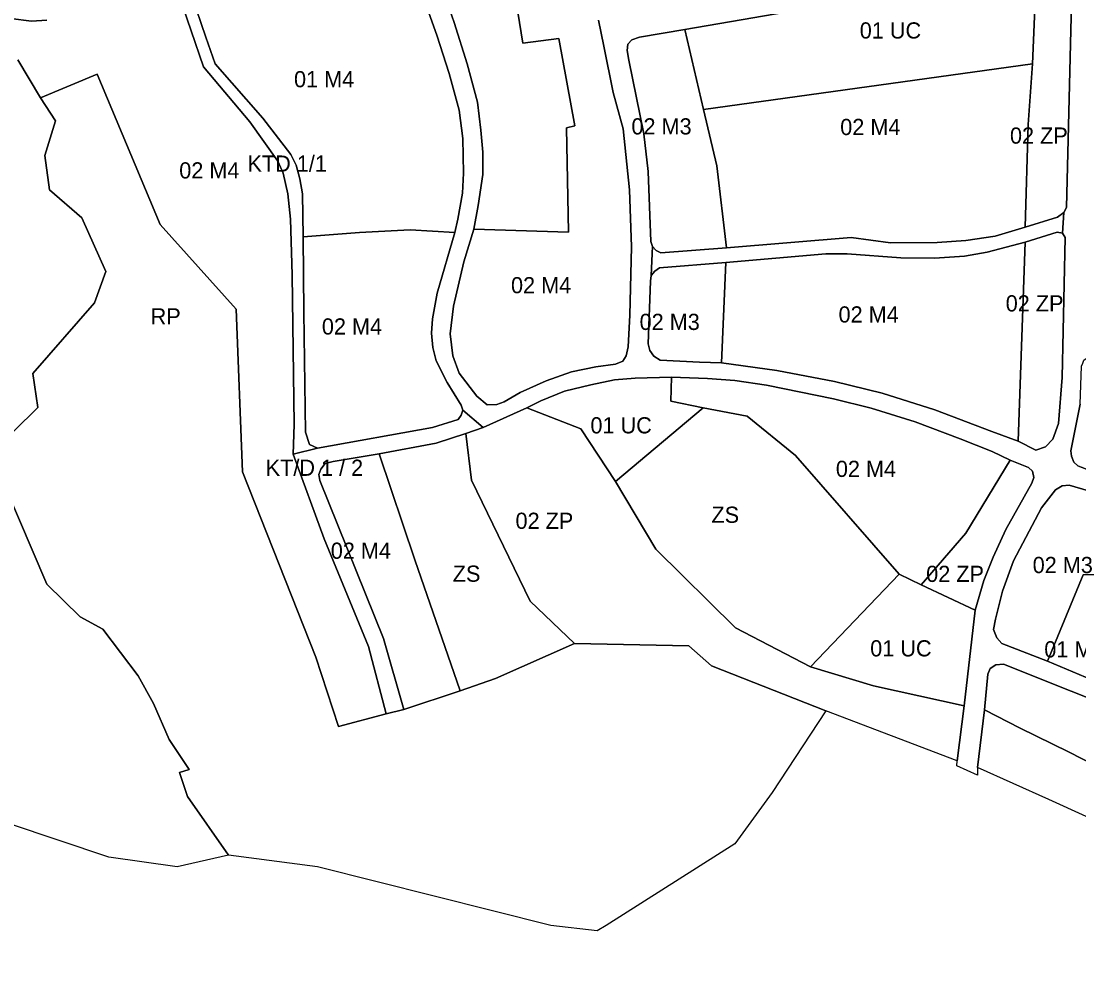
# Model space of a CAD drawing. Extents: x 7419295 to 7421535, y 5544294 to 5545394.
# Drawn here: x 7420075 to 7420728, y 5544294 to 5544875 of the extents above; entities that cross this region are included whole.
import ezdxf

# ---------------------------------------------------------------- set-up
doc = ezdxf.new("R2010")
doc.units = 0
doc.layers.add('linie_rozgraniczajace', color=7, linetype='Continuous')
doc.layers.add('oznaczenia_przeznaczen', color=7, linetype='Continuous')

msp = doc.modelspace()

# ---------------------------------------------------------------- linework, layer by layer
at = {"layer": 'linie_rozgraniczajace'}
for points in [[(7420374.46, 5544927.64), (7420385.1, 5544861.32), (7420407.25, 5544864.01), (7420417.22, 5544810.2), (7420412.02, 5544808.94), (7420413.37, 5544744.51), (7420354.78, 5544746.31), (7420357.53, 5544760.98), (7420360.41, 5544780.03), (7420360.33, 5544793.87), (7420359.14, 5544807.54), (7420357.01, 5544824.75), (7420350.66, 5544848.44), (7420342.78, 5544874.06), (7420338.31, 5544886.26)], [(7420431.9, 5544875.41), (7420435.21, 5544859.45), (7420440.83, 5544830.75), (7420446.99, 5544808.25), (7420450.9, 5544770.69), (7420452.17, 5544735.47), (7420451.18, 5544693.29), (7420450.07, 5544673.71), (7420448.87, 5544668), (7420446.77, 5544664.78), (7420442.4, 5544662.96), (7420430.22, 5544661.27), (7420415.08, 5544658.12), (7420399.56, 5544652.72), (7420383.48, 5544645.51), (7420373.54, 5544639.59), (7420369.03, 5544637.93), (7420363.15, 5544637.84), (7420356.74, 5544643.09), (7420345.82, 5544657.41), (7420341.89, 5544668.14), (7420340.22, 5544681.64), (7420342.23, 5544698.72), (7420348.6, 5544726.22), (7420354.78, 5544746.31), (7420413.37, 5544744.51), (7420412.02, 5544808.94), (7420417.22, 5544810.2), (7420407.25, 5544864.01), (7420385.1, 5544861.32), (7420374.46, 5544927.64)], [(7420165.01, 5544913.57), (7420187.81, 5544846.67), (7420216.52, 5544812.6), (7420233.88, 5544788.26), (7420237.03, 5544780.84), (7420240.08, 5544768.14), (7420241.67, 5544752.56), (7420242.75, 5544718.16), (7420243.81, 5544625.59), (7420243.27, 5544607.43), (7420262.51, 5544555.08), (7420289.85, 5544488.58), (7420300.75, 5544446.91), (7420271.19, 5544439.15), (7420257.37, 5544481.96), (7420211.94, 5544596.44), (7420208.05, 5544696.89), (7420161.14, 5544749.31), (7420122.29, 5544841.99), (7420087.27, 5544827.45), (7420073.18, 5544850.83)], [(7420327.05, 5544879.92), (7420332.06, 5544866.11), (7420339.7, 5544842.42), (7420345.83, 5544819.78), (7420348.12, 5544802.43), (7420348.52, 5544780.83), (7420347.91, 5544768.5), (7420344.9, 5544752.58), (7420343.05, 5544744.3), (7420315.48, 5544746.02), (7420284.29, 5544744.29), (7420249.53, 5544741.55), (7420249.09, 5544768.07), (7420247.44, 5544777.4), (7420245.19, 5544785.8), (7420241.9, 5544792.53), (7420224.45, 5544814.92), (7420195.18, 5544848.39), (7420189.26, 5544864.99), (7420171.71, 5544917.12)], [(7420702.29, 5544907.09), (7420485.05, 5544869.73), (7420457.22, 5544865), (7420452.36, 5544863.31), (7420449.93, 5544860.53), (7420449.61, 5544856.64), (7420450.64, 5544850.72), (7420459.8, 5544805.21), (7420462.48, 5544782.05), (7420464.24, 5544738.77), (7420465.17, 5544735.53), (7420464.43, 5544717.7), (7420463.93, 5544714.25), (7420462.48, 5544675.57), (7420463.44, 5544671.44), (7420465.97, 5544667.81), (7420469.89, 5544665.43), (7420494.27, 5544664.19), (7420507.8, 5544663.69), (7420542.02, 5544659.12), (7420577.6, 5544652.21), (7420607.03, 5544645.1), (7420639.57, 5544634.79), (7420674.62, 5544621.3), (7420690.93, 5544615.3), (7420701.8, 5544609.92), (7420707.76, 5544611.96), (7420712.34, 5544616.62), (7420715.92, 5544626.3), (7420718.1, 5544654.8), (7420719.99, 5544741.28), (7420718.29, 5544743.9), (7420719.21, 5544756.58), (7420720.83, 5544759.77), (7420724.4, 5544903.07)], [(7420338.31, 5544886.26), (7420342.78, 5544874.06), (7420350.66, 5544848.44), (7420357.01, 5544824.75), (7420359.14, 5544807.54), (7420360.33, 5544793.87), (7420360.41, 5544780.03), (7420357.53, 5544760.98), (7420354.78, 5544746.31), (7420348.6, 5544726.22), (7420342.23, 5544698.72), (7420340.22, 5544681.64), (7420341.89, 5544668.14), (7420345.82, 5544657.41), (7420356.74, 5544643.09), (7420363.15, 5544637.84), (7420369.03, 5544637.93), (7420373.54, 5544639.59), (7420383.48, 5544645.51), (7420399.56, 5544652.72), (7420415.08, 5544658.12), (7420430.22, 5544661.27), (7420442.4, 5544662.96), (7420446.77, 5544664.78), (7420448.87, 5544668), (7420450.07, 5544673.71), (7420451.18, 5544693.29), (7420452.17, 5544735.47), (7420450.9, 5544770.69), (7420446.99, 5544808.25), (7420440.83, 5544830.75), (7420435.21, 5544859.45), (7420431.9, 5544875.41)], [(7420765.57, 5544444.2), (7420681.96, 5544477.58), (7420677.2, 5544477.24), (7420673.64, 5544475.01), (7420672.35, 5544471.53), (7420670.12, 5544449.36), (7420665.8, 5544413.78), (7420665.83, 5544409.16), (7420653.2, 5544414.91), (7420653.23, 5544417.89), (7420657.65, 5544451.83), (7420664.46, 5544510.93), (7420669.76, 5544529.29), (7420675.54, 5544543.69), (7420683.27, 5544560.85), (7420699.43, 5544589.53), (7420700.72, 5544593.01), (7420699.93, 5544596.85), (7420697.45, 5544599.14), (7420686.14, 5544603.55), (7420674.96, 5544608.91), (7420655.08, 5544616.9), (7420627.32, 5544627.25), (7420600.18, 5544635.81), (7420576.9, 5544641.58), (7420535.55, 5544649.89), (7420516.03, 5544652.82), (7420499.19, 5544654.08), (7420476.85, 5544654.96), (7420454.46, 5544654.34), (7420441.63, 5544653.23), (7420427.13, 5544650.25), (7420410.81, 5544646.17), (7420396.27, 5544640.21), (7420387.62, 5544636.01), (7420360.62, 5544623.73), (7420348.1, 5544634.49), (7420347.02, 5544637.58), (7420338.34, 5544651.69), (7420331.61, 5544664.91), (7420329.53, 5544673.17), (7420328.69, 5544682.08), (7420329.28, 5544690.9), (7420332.14, 5544706.82), (7420343.05, 5544744.3), (7420344.9, 5544752.58), (7420347.91, 5544768.5), (7420348.52, 5544780.83), (7420348.12, 5544802.43), (7420345.83, 5544819.78), (7420339.7, 5544842.42), (7420332.06, 5544866.11), (7420327.05, 5544879.92)], [(7420091.1, 5544875.41), (7420081.59, 5544874.72), (7420068.64, 5544876.43)], [(7420068.64, 5544876.43), (7420081.59, 5544874.72), (7420091.1, 5544875.41)], [(7420073.18, 5544850.83), (7420087.27, 5544827.45), (7420096.43, 5544813.21), (7420089.83, 5544791.78), (7420092.76, 5544770.63), (7420112.86, 5544753.26), (7420127.55, 5544720.18), (7420120.54, 5544700.9), (7420082.58, 5544657.18), (7420085.66, 5544636.14), (7420070.72, 5544621.63)], [(7420070.72, 5544621.63), (7420085.66, 5544636.14), (7420082.58, 5544657.18), (7420120.54, 5544700.9), (7420127.55, 5544720.18), (7420112.86, 5544753.26), (7420092.76, 5544770.63), (7420089.83, 5544791.78), (7420096.43, 5544813.21), (7420087.27, 5544827.45), (7420122.29, 5544841.99), (7420161.14, 5544749.31), (7420208.05, 5544696.89), (7420211.94, 5544596.44), (7420257.37, 5544481.96), (7420271.19, 5544439.15), (7420300.75, 5544446.91), (7420311.61, 5544449.59), (7420346.34, 5544461.24), (7420368.29, 5544468.84), (7420417.09, 5544490.35), (7420487.55, 5544489.03), (7420501.68, 5544476.53), (7420572.17, 5544448.84), (7420539.01, 5544398.27), (7420516.02, 5544366.62), (7420436.53, 5544316.31), (7420430.9, 5544312.97), (7420402.38, 5544316.13), (7420258.34, 5544352.37), (7420203.36, 5544359.58), (7420178.05, 5544395.97), (7420172.99, 5544410.81), (7420179.12, 5544412.6), (7420166.61, 5544431.02), (7420157.12, 5544453.29), (7420147.52, 5544470.49), (7420125.74, 5544499.19), (7420111.76, 5544506.96), (7420091.08, 5544526.99), (7420065.25, 5544587.88)], [(7420729.31, 5544638.3), (7420723.57, 5544609.33), (7420723.82, 5544606.16), (7420725.42, 5544602.47), (7420727.82, 5544600.06), (7420742.24, 5544594.51)], [(7420065.25, 5544587.88), (7420091.08, 5544526.99), (7420111.76, 5544506.96), (7420125.74, 5544499.19), (7420147.52, 5544470.49), (7420157.12, 5544453.29), (7420166.61, 5544431.02), (7420179.12, 5544412.6), (7420172.99, 5544410.81), (7420178.05, 5544395.97), (7420203.36, 5544359.58), (7420171.7, 5544352.49), (7420129.5, 5544358.52), (7420067.4, 5544379.25)], [(7420734.48, 5544584.68), (7420722.45, 5544588.18), (7420718.1, 5544587.89), (7420713.96, 5544585.33), (7420705.31, 5544574.17), (7420688.09, 5544541.39), (7420681.32, 5544522.77), (7420676.93, 5544505.53), (7420675.74, 5544499), (7420677.76, 5544493.96), (7420680.94, 5544490.34), (7420709.11, 5544479.54), (7420748.11, 5544463.04)], [(7420747.77, 5544410.39), (7420722.04, 5544423.59), (7420692.2, 5544438.03), (7420670.12, 5544449.36), (7420672.35, 5544471.53), (7420673.64, 5544475.01), (7420677.2, 5544477.24), (7420681.96, 5544477.58), (7420765.57, 5544444.2)]]:
    msp.add_lwpolyline(points, dxfattribs=at)
for points in [[(7420171.71, 5544917.12), (7420189.26, 5544864.99), (7420195.18, 5544848.39), (7420224.45, 5544814.92), (7420241.9, 5544792.53), (7420245.19, 5544785.8), (7420247.44, 5544777.4), (7420249.09, 5544768.07), (7420249.53, 5544741.55), (7420249.89, 5544695.06), (7420250.83, 5544620.86), (7420253.36, 5544613.36), (7420258.39, 5544611.02), (7420243.27, 5544607.43), (7420243.81, 5544625.59), (7420242.75, 5544718.16), (7420241.67, 5544752.56), (7420240.08, 5544768.14), (7420237.03, 5544780.84), (7420233.88, 5544788.26), (7420216.52, 5544812.6), (7420187.81, 5544846.67), (7420165.01, 5544913.57)], [(7420702.29, 5544907.09), (7420699.74, 5544848.48), (7420496.72, 5544820.31), (7420485.05, 5544869.73)], [(7420702.29, 5544907.09), (7420715.71, 5544909.42), (7420719.53, 5544909.43), (7420722.29, 5544907.9), (7420724.4, 5544903.07), (7420720.83, 5544759.77), (7420719.21, 5544756.58), (7420715.35, 5544753.73), (7420695.25, 5544747.55), (7420697.13, 5544811), (7420699.74, 5544848.48)], [(7420485.05, 5544869.73), (7420496.72, 5544820.31), (7420504.95, 5544785.44), (7420510.96, 5544734.83), (7420470.25, 5544731.71), (7420467.34, 5544733.08), (7420465.17, 5544735.53), (7420464.24, 5544738.77), (7420462.48, 5544782.05), (7420459.8, 5544805.21), (7420450.64, 5544850.72), (7420449.61, 5544856.64), (7420449.93, 5544860.53), (7420452.36, 5544863.31), (7420457.22, 5544865)], [(7420699.74, 5544848.48), (7420697.13, 5544811), (7420695.25, 5544747.55), (7420676.71, 5544742.06), (7420658.7, 5544739.24), (7420641.01, 5544738.07), (7420612.09, 5544737.79), (7420587.78, 5544741.13), (7420510.96, 5544734.83), (7420504.95, 5544785.44), (7420496.72, 5544820.31)], [(7420719.21, 5544756.58), (7420718.29, 5544743.9), (7420715.09, 5544744.51), (7420695.3, 5544738.34), (7420671.89, 5544732.1), (7420657.84, 5544729.59), (7420639.28, 5544728.39), (7420618.6, 5544728.6), (7420585.42, 5544731.13), (7420572.17, 5544731.02), (7420510.37, 5544725.82), (7420469.48, 5544722.38), (7420466.54, 5544720.47), (7420464.43, 5544717.7), (7420465.17, 5544735.53), (7420467.34, 5544733.08), (7420470.25, 5544731.71), (7420510.96, 5544734.83), (7420587.78, 5544741.13), (7420612.09, 5544737.79), (7420641.01, 5544738.07), (7420658.7, 5544739.24), (7420676.71, 5544742.06), (7420695.25, 5544747.55), (7420715.35, 5544753.73)], [(7420249.53, 5544741.55), (7420284.29, 5544744.29), (7420315.48, 5544746.02), (7420343.05, 5544744.3), (7420332.14, 5544706.82), (7420329.28, 5544690.9), (7420328.69, 5544682.08), (7420329.53, 5544673.17), (7420331.61, 5544664.91), (7420338.34, 5544651.69), (7420347.02, 5544637.58), (7420348.1, 5544634.49), (7420347.11, 5544631.47), (7420345.16, 5544628.71), (7420329.3, 5544623.74), (7420258.39, 5544611.02), (7420253.36, 5544613.36), (7420250.83, 5544620.86), (7420249.89, 5544695.06)], [(7420695.3, 5544738.34), (7420715.09, 5544744.51), (7420718.29, 5544743.9), (7420719.99, 5544741.28), (7420718.1, 5544654.8), (7420715.92, 5544626.3), (7420712.34, 5544616.62), (7420707.76, 5544611.96), (7420701.8, 5544609.92), (7420690.93, 5544615.3)], [(7420695.3, 5544738.34), (7420690.93, 5544615.3), (7420674.62, 5544621.3), (7420639.57, 5544634.79), (7420607.03, 5544645.1), (7420577.6, 5544652.21), (7420542.02, 5544659.12), (7420507.8, 5544663.69), (7420510.37, 5544725.82), (7420572.17, 5544731.02), (7420585.42, 5544731.13), (7420618.6, 5544728.6), (7420639.28, 5544728.39), (7420657.84, 5544729.59), (7420671.89, 5544732.1)], [(7420510.37, 5544725.82), (7420507.8, 5544663.69), (7420494.27, 5544664.19), (7420469.89, 5544665.43), (7420465.97, 5544667.81), (7420463.44, 5544671.44), (7420462.48, 5544675.57), (7420463.93, 5544714.25), (7420464.43, 5544717.7), (7420466.54, 5544720.47), (7420469.48, 5544722.38)], [(7420729.8, 5544599.3), (7420727.82, 5544600.06), (7420725.42, 5544602.47), (7420723.82, 5544606.16), (7420723.57, 5544609.33), (7420729.31, 5544638.3), (7420730.05, 5544661.76), (7420730.83, 5544663.56), (7420731.6, 5544665.35), (7420734.43, 5544667.4), (7420738.4, 5544668.36), (7420742.14, 5544668.48), (7420754.99, 5544668.92), (7420767.61, 5544670.3), (7420769.36, 5544670.59), (7420770.8, 5544660.04), (7420772.41, 5544648.31), (7420774.03, 5544636.54), (7420774.32, 5544634.42), (7420780.19, 5544595.04), (7420780.62, 5544592.32), (7420760.67, 5544591.73), (7420742.24, 5544594.51)], [(7420387.62, 5544636.01), (7420396.27, 5544640.21), (7420410.81, 5544646.17), (7420427.13, 5544650.25), (7420441.63, 5544653.23), (7420454.46, 5544654.34), (7420476.85, 5544654.96), (7420476.5, 5544640.18), (7420496.51, 5544635.95), (7420442.32, 5544590.41), (7420420.9, 5544622.9)], [(7420476.85, 5544654.96), (7420499.19, 5544654.08), (7420516.03, 5544652.82), (7420535.55, 5544649.89), (7420576.9, 5544641.58), (7420600.18, 5544635.81), (7420627.32, 5544627.25), (7420655.08, 5544616.9), (7420674.96, 5544608.91), (7420686.14, 5544603.55), (7420658.72, 5544558.51), (7420631.07, 5544526.72), (7420617.6, 5544533.33), (7420553.47, 5544606.55), (7420523.58, 5544630.79), (7420496.51, 5544635.95), (7420476.5, 5544640.18)], [(7420348.1, 5544634.49), (7420360.62, 5544623.73), (7420349.8, 5544620.02), (7420331.6, 5544614.06), (7420296.31, 5544607.57), (7420268.05, 5544602.84), (7420263.01, 5544601.6), (7420260.45, 5544598.06), (7420259.15, 5544594.88), (7420259.78, 5544591.18), (7420299.02, 5544493.57), (7420311.61, 5544449.59), (7420300.75, 5544446.91), (7420289.85, 5544488.58), (7420262.51, 5544555.08), (7420243.27, 5544607.43), (7420258.39, 5544611.02), (7420329.3, 5544623.74), (7420345.16, 5544628.71), (7420347.11, 5544631.47)], [(7420387.62, 5544636.01), (7420420.9, 5544622.9), (7420442.32, 5544590.41), (7420467.22, 5544548.64), (7420516.52, 5544500.16), (7420562.64, 5544475.94), (7420601.67, 5544464.32), (7420657.65, 5544451.83), (7420653.23, 5544417.89), (7420572.17, 5544448.84), (7420501.68, 5544476.53), (7420487.55, 5544489.03), (7420417.09, 5544490.35), (7420389.61, 5544516.48), (7420353.35, 5544591.27), (7420349.8, 5544620.02), (7420360.62, 5544623.73)], [(7420496.51, 5544635.95), (7420523.58, 5544630.79), (7420553.47, 5544606.55), (7420617.6, 5544533.33), (7420562.64, 5544475.94), (7420516.52, 5544500.16), (7420467.22, 5544548.64), (7420442.32, 5544590.41)], [(7420349.8, 5544620.02), (7420353.35, 5544591.27), (7420389.61, 5544516.48), (7420417.09, 5544490.35), (7420368.29, 5544468.84), (7420346.34, 5544461.24), (7420318.36, 5544542.12), (7420296.31, 5544607.57), (7420331.6, 5544614.06)], [(7420296.31, 5544607.57), (7420318.36, 5544542.12), (7420346.34, 5544461.24), (7420311.61, 5544449.59), (7420299.02, 5544493.57), (7420259.78, 5544591.18), (7420259.15, 5544594.88), (7420260.45, 5544598.06), (7420263.01, 5544601.6), (7420268.05, 5544602.84)], [(7420686.14, 5544603.55), (7420697.45, 5544599.14), (7420699.93, 5544596.85), (7420700.72, 5544593.01), (7420699.43, 5544589.53), (7420683.27, 5544560.85), (7420675.54, 5544543.69), (7420669.76, 5544529.29), (7420664.46, 5544510.93), (7420631.07, 5544526.72), (7420658.72, 5544558.51)], [(7420709.11, 5544479.54), (7420680.94, 5544490.34), (7420677.76, 5544493.96), (7420675.74, 5544499), (7420676.93, 5544505.53), (7420681.32, 5544522.77), (7420688.09, 5544541.39), (7420705.31, 5544574.17), (7420713.96, 5544585.33), (7420718.1, 5544587.89), (7420722.45, 5544588.18), (7420734.48, 5544584.68), (7420748.03, 5544582.62), (7420757.7, 5544533.42), (7420731.09, 5544532.76)], [(7420617.6, 5544533.33), (7420631.07, 5544526.72), (7420664.46, 5544510.93), (7420657.65, 5544451.83), (7420601.67, 5544464.32), (7420562.64, 5544475.94)], [(7420709.11, 5544479.54), (7420731.09, 5544532.76), (7420757.7, 5544533.42), (7420754.93, 5544521.74), (7420759.52, 5544471.69), (7420759.11, 5544466.9), (7420756.45, 5544463.83), (7420752.39, 5544462.19), (7420748.11, 5544463.04)], [(7420670.12, 5544449.36), (7420692.2, 5544438.03), (7420722.04, 5544423.59), (7420747.77, 5544410.39), (7420820.92, 5544386.38), (7420875.33, 5544367.46), (7420915.14, 5544354.02), (7420969.38, 5544336.28), (7420988.63, 5544339.74), (7420995.22, 5544336.76), (7421005.3, 5544335.08), (7421013.71, 5544335.42), (7421020.97, 5544336.76), (7421026.15, 5544334.44), (7421028.68, 5544330.81), (7421037.09, 5544302.2), (7421017.41, 5544299.9), (7420951.2, 5544294.38), (7420897.99, 5544301.46), (7420781.41, 5544361.51), (7420710, 5544394.09), (7420665.8, 5544413.78)]]:
    msp.add_lwpolyline(points, close=True, dxfattribs=at)

# ---------------------------------------------------------------- texts
at = {"layer": 'oznaczenia_przeznaczen'}
for s, p in [('01 UC', (7420593.15, 5544864.09)), ('01 M4', (7420243.81, 5544833.97)), ('02 M3', (7420452.17, 5544804.83)), ('02 M4', (7420581.11, 5544804.46)), ('02 ZP', (7420685.93, 5544799.15)), ('02 M4', (7420172.93, 5544777.64)), ('KTD 1/1', (7420215.05, 5544781.85)), ('02 M4', (7420377.8, 5544706.73)), ('02 ZP', (7420683.29, 5544695.51)), ('RP', (7420155.27, 5544687.48)), ('02 M4', (7420580.06, 5544688.66)), ('02 M4', (7420261, 5544681.24)), ('02 M3', (7420457.21, 5544684.06)), ('01 UC', (7420426.85, 5544620.18)), ('KT/D 1 / 2', (7420226.3, 5544593.97)), ('02 M4', (7420578.4, 5544593.28)), ('ZS', (7420501.57, 5544564.94)), ('02 ZP', (7420380.58, 5544561.21)), ('02 M4', (7420266.5, 5544542.73)), ('02 M3', (7420699.95, 5544533.9)), ('ZS', (7420341.82, 5544528.54)), ('02 ZP', (7420634.18, 5544528.43)), ('01 UC', (7420599.62, 5544482.42)), ('01 M3', (7420707.12, 5544481.81))]:
    msp.add_text(s, height=10, dxfattribs=at).set_placement(p)

doc.saveas('drawing.dxf')
